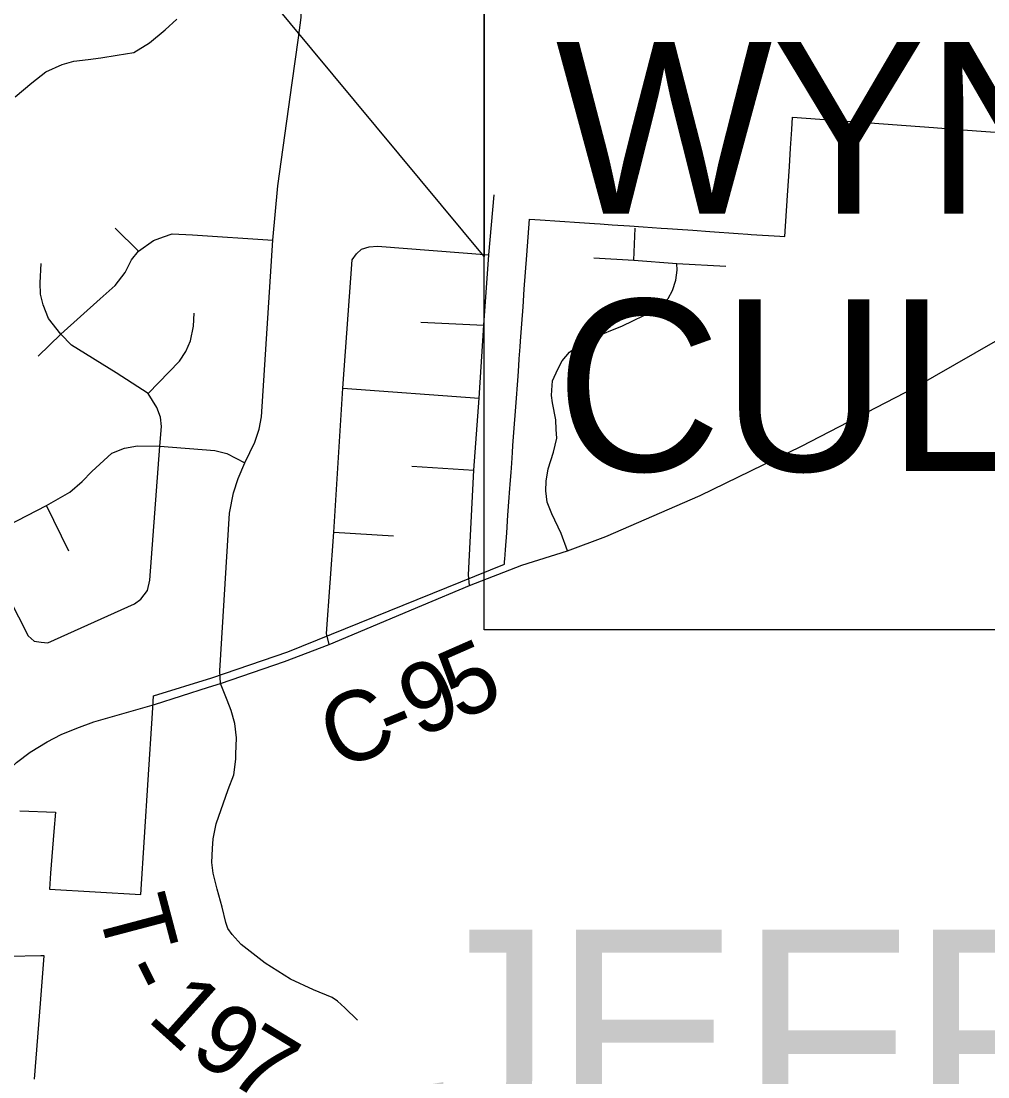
# Model space of a CAD drawing. Extents: x 208586767.6 to 208586821.4, y -134301046.9 to -134301022.9.
# Drawn here: x 208586780.726 to 208586781.515, y -134301029.317 to -134301028.455 of the extents above; entities that cross this region are included whole.
import ezdxf

# ---------------------------------------------------------------- set-up
doc = ezdxf.new("R2010")
doc.units = 0
for name, color, linetype in [('GM_X_City_Street', 7, 'Continuous'), ('GM_X_Corporation', 7, 'Continuous'), ('GM_X_County_Road', 7, 'Continuous'), ('GM_X_County_Road_Text', 7, 'Continuous'), ('GM_X_Minor_River', 7, 'Continuous'), ('GM_X_Township_Road', 7, 'Continuous'), ('GM_X_Township_Road_Text', 7, 'Continuous'), ('GM_X_Township_Text', 7, 'Continuous'), ('SH_Text', 7, 'Continuous')]:
    doc.layers.add(name, color=color, linetype=linetype)

msp = doc.modelspace()

# ---------------------------------------------------------------- linework, layer by layer
at = {"layer": 'GM_X_City_Street'}
for p, q in [((208586780.80313, -134301028.62414), (208586780.82208, -134301028.64308)), ((208586781.05241, -134301028.70091), (208586781.10392, -134301028.70348)), ((208586780.74037, -134301028.72874), (208586780.75892, -134301028.71058)), ((208586780.98885, -134301028.75479), (208586781.09997, -134301028.76289)), ((208586781.0451, -134301028.81854), (208586781.09563, -134301028.8217)), ((208586780.76524, -134301028.88782), (208586780.74702, -134301028.85063)), ((208586780.98155, -134301028.87222), (208586781.0301, -134301028.87538))]:
    msp.add_line(p, q, dxfattribs=at)
for points in [[(208586781.09227, -134301028.91585), (208586781.09122, -134301028.90716), (208586781.09563, -134301028.8217), (208586781.09997, -134301028.76289), (208586781.10392, -134301028.70348), (208586781.10806, -134301028.64605), (208586781.11221, -134301028.5971)], [(208586780.75892, -134301028.71058), (208586780.7909, -134301028.68177), (208586780.80313, -134301028.67111), (208586780.81142, -134301028.66046), (208586780.81655, -134301028.65019), (208586780.82208, -134301028.64308), (208586780.83432, -134301028.6344), (208586780.84261, -134301028.63125), (208586780.84971, -134301028.62888), (208586780.86629, -134301028.62967), (208586780.93182, -134301028.634)], [(208586780.97761, -134301028.9638), (208586780.97549, -134301028.95505), (208586780.98155, -134301028.87222), (208586780.98885, -134301028.75479), (208586780.99655, -134301028.64999), (208586780.99991, -134301028.64526), (208586781.00405, -134301028.64131), (208586781.01037, -134301028.63934), (208586781.01708, -134301028.63894), (208586781.10806, -134301028.64605)], [(208586780.6922, -134301028.87867), (208586780.73209, -134301028.95689), (208586780.73721, -134301028.96124), (208586780.74274, -134301028.96203), (208586780.74827, -134301028.96242), (208586780.81892, -134301028.93084), (208586780.82405, -134301028.92689), (208586780.82958, -134301028.91979), (208586780.83155, -134301028.9115), (208586780.83945, -134301028.80216), (208586780.84103, -134301028.78598), (208586780.84024, -134301028.77848), (208586780.83708, -134301028.77058), (208586780.82998, -134301028.75914), (208586780.80392, -134301028.74216), (208586780.76761, -134301028.71966), (208586780.75892, -134301028.71058), (208586780.74866, -134301028.69796), (208586780.74432, -134301028.6869), (208586780.74234, -134301028.67821), (208586780.74195, -134301028.66874), (208586780.74274, -134301028.65296)], [(208586780.82998, -134301028.75914), (208586780.85563, -134301028.73269), (208586780.86076, -134301028.72479), (208586780.86471, -134301028.71611), (208586780.86708, -134301028.70427), (208586780.86748, -134301028.69361)], [(208586780.57247, -134301028.91554), (208586780.59138, -134301028.9168), (208586780.60461, -134301028.91617), (208586780.62698, -134301028.91082), (208586780.6922, -134301028.87867), (208586780.74702, -134301028.85063), (208586780.76603, -134301028.83966), (208586780.77629, -134301028.83098), (208586780.78419, -134301028.82269), (208586780.80037, -134301028.80769), (208586780.81063, -134301028.80374), (208586780.82129, -134301028.80177), (208586780.83945, -134301028.80216), (208586780.88445, -134301028.80571), (208586780.89432, -134301028.80808), (208586780.90892, -134301028.81558)]]:
    msp.add_lwpolyline(points, dxfattribs=at)
at = {"layer": 'GM_X_Corporation'}
for points in [[(208586780.72535, -134301029.09969), (208586780.7544, -134301029.10066), (208586780.75316, -134301029.11655), (208586780.75051, -134301029.15048), (208586780.74948, -134301029.16362), (208586780.8242, -134301029.16794), (208586780.83018, -134301029.07445), (208586780.83366, -134301029.01994), (208586780.83454, -134301029.0057), (208586780.88194, -134301028.99115), (208586780.94385, -134301028.96983), (208586781.12063, -134301028.89836), (208586781.12078, -134301028.89625), (208586781.12092, -134301028.89424), (208586781.12146, -134301028.88677), (208586781.12248, -134301028.87271), (208586781.12353, -134301028.85832), (208586781.12456, -134301028.84397), (208586781.12483, -134301028.84027), (208586781.12558, -134301028.82991), (208586781.12604, -134301028.82346), (208586781.12658, -134301028.81603), (208586781.12722, -134301028.80719), (208586781.12763, -134301028.8015), (208586781.12814, -134301028.7945), (208586781.12865, -134301028.78738), (208586781.12966, -134301028.77351), (208586781.13068, -134301028.75936), (208586781.13095, -134301028.75565), (208586781.13173, -134301028.74487), (208586781.13232, -134301028.73662), (208586781.13275, -134301028.73076), (208586781.13345, -134301028.72106), (208586781.13378, -134301028.7165), (208586781.13481, -134301028.70231), (208586781.13581, -134301028.68839), (208586781.13685, -134301028.67409), (208586781.13785, -134301028.66026), (208586781.13886, -134301028.64624), (208586781.13992, -134301028.63165), (208586781.14099, -134301028.61682), (208586781.14984, -134301028.61742), (208586781.16594, -134301028.61853), (208586781.18189, -134301028.61962), (208586781.19423, -134301028.62047), (208586781.19861, -134301028.62077), (208586781.2084, -134301028.62144), (208586781.22257, -134301028.62241), (208586781.23391, -134301028.6232), (208586781.24852, -134301028.6242), (208586781.25378, -134301028.62456), (208586781.26175, -134301028.62511), (208586781.27435, -134301028.62598), (208586781.2883, -134301028.62694), (208586781.31135, -134301028.62853), (208586781.31919, -134301028.62907), (208586781.32202, -134301028.62926), (208586781.3454, -134301028.63087), (208586781.34942, -134301028.63115), (208586781.35156, -134301028.59762), (208586781.35308, -134301028.57398), (208586781.35404, -134301028.55888), (208586781.35501, -134301028.54382), (208586781.35566, -134301028.53359), (208586781.4706, -134301028.54212), (208586781.48741, -134301028.54337), (208586781.50558, -134301028.54472), (208586781.55151, -134301028.54813)], [(208586780.73736, -134301029.31845), (208586780.74218, -134301029.25686), (208586780.74522, -134301029.21801), (208586780.74239, -134301029.21806), (208586780.69045, -134301029.21895)]]:
    msp.add_lwpolyline(points, dxfattribs=at)
at = {"layer": 'GM_X_County_Road'}
msp.add_line((208586780.82195, -134301029.01662), (208586780.8315, -134301029.01393), dxfattribs=at)
for points in [[(208586780.87936, -134301028.99874), (208586780.88894, -134301028.99567), (208586780.94113, -134301028.9779), (208586780.97761, -134301028.9638), (208586781.0532, -134301028.93222), (208586781.09227, -134301028.91585), (208586781.13471, -134301028.89907), (208586781.17201, -134301028.88742), (208586781.20339, -134301028.87578), (208586781.28036, -134301028.84223), (208586781.36304, -134301028.8022), (208586781.45498, -134301028.7545), (208586781.5378, -134301028.70682)], [(208586780.8315, -134301029.01393), (208586780.83533, -134301029.01286), (208586780.87936, -134301028.99874)], [(208586780.69431, -134301029.08799), (208586780.69704, -134301029.08484), (208586780.70476, -134301029.0768), (208586780.72274, -134301029.06008), (208586780.73394, -134301029.05188), (208586780.74766, -134301029.04321), (208586780.75901, -134301029.03745), (208586780.77194, -134301029.03209), (208586780.78565, -134301029.02689), (208586780.80284, -134301029.022), (208586780.82195, -134301029.01662)]]:
    msp.add_lwpolyline(points, dxfattribs=at)
at = {"layer": 'GM_X_Minor_River'}
msp.add_lwpolyline([(208586780.7217, -134301028.51704), (208586780.73505, -134301028.50573), (208586780.74649, -134301028.49669), (208586780.75981, -134301028.4907), (208586780.76932, -134301028.4881), (208586780.78109, -134301028.48665), (208586780.79135, -134301028.48519), (208586780.80465, -134301028.483), (208586780.81832, -134301028.4808), (208586780.83128, -134301028.47291), (208586780.84387, -134301028.46236), (208586780.85341, -134301028.45368)], dxfattribs=at)
at = {"layer": 'GM_X_Township_Road'}
for p, q in [((208586781.22609, -134301028.65039), (208586781.22727, -134301028.62434)), ((208586781.26122, -134301028.65315), (208586781.30128, -134301028.65532))]:
    msp.add_line(p, q, dxfattribs=at)
for points in [[(208586780.88854, -134301028.98536), (208586780.89629, -134301028.85663), (208586780.89979, -134301028.84028), (208586780.90344, -134301028.82837), (208586780.90892, -134301028.81558), (208586780.91705, -134301028.79872), (208586780.9207, -134301028.78827), (208586780.9224, -134301028.77806), (208586780.93182, -134301028.634), (208586780.9359, -134301028.58979), (208586780.94741, -134301028.50557), (208586780.95257, -134301028.46896), (208586780.95481, -134301028.45229), (208586780.95532, -134301028.43304), (208586780.95515, -134301028.41723), (208586780.9537, -134301028.38523)], [(208586781.19352, -134301028.64841), (208586781.22609, -134301028.65039), (208586781.26122, -134301028.65315)], [(208586781.17201, -134301028.88742), (208586781.16688, -134301028.87341), (208586781.15938, -134301028.85723), (208586781.15563, -134301028.84776), (208586781.15444, -134301028.83867), (208586781.15464, -134301028.83078), (208586781.15642, -134301028.82071), (208586781.16056, -134301028.8069), (208586781.16332, -134301028.79545), (208586781.16293, -134301028.78855), (208586781.16253, -134301028.78065), (208586781.15977, -134301028.76664), (208586781.15898, -134301028.76071), (208586781.15938, -134301028.75637), (208586781.15997, -134301028.74887), (208586781.16431, -134301028.7392), (208586781.16786, -134301028.73249), (208586781.17379, -134301028.72539), (208586781.18089, -134301028.71986), (208586781.19273, -134301028.71374), (208586781.21701, -134301028.70387), (208586781.24286, -134301028.69144), (208586781.24859, -134301028.68729), (208586781.25411, -134301028.68157), (208586781.25786, -134301028.67506), (208586781.26043, -134301028.66657), (208586781.26141, -134301028.65848), (208586781.26122, -134301028.65315)], [(208586780.90161, -134301029.05334), (208586780.90211, -134301029.04003), (208586780.90081, -134301029.0285), (208586780.8978, -134301029.01781), (208586780.89461, -134301029.00937), (208586780.88894, -134301028.99567), (208586780.88854, -134301028.98536)], [(208586781.00068, -134301029.27047), (208586780.99046, -134301029.26025), (208586780.98458, -134301029.25502), (208586780.98001, -134301029.25198), (208586780.96499, -134301029.24567), (208586780.94607, -134301029.23696), (208586780.92561, -134301029.22391), (208586780.90603, -134301029.20867), (208586780.89862, -134301029.20063), (208586780.89493, -134301029.19562), (208586780.89341, -134301029.19083), (208586780.89036, -134301029.17821), (208586780.88644, -134301029.16363), (208586780.88296, -134301029.15036), (208586780.88187, -134301029.14187), (208586780.88253, -134301029.13034), (208586780.88296, -134301029.1225), (208586780.88557, -134301029.1101), (208586780.89536, -134301029.08225), (208586780.89993, -134301029.07028), (208586780.90146, -134301029.05744), (208586780.90161, -134301029.05334)]]:
    msp.add_lwpolyline(points, dxfattribs=at)
at = {"layer": 'SH_Text'}
for points in [[(208586781.10405, -134301028.37904), (208586781.10405, -134301028.64742), (208586780.48945, -134301027.90753)], [(208586781.10405, -134301028.37904), (208586783.37296, -134301028.37904), (208586783.37296, -134301028.95195), (208586781.10405, -134301028.95195)]]:
    msp.add_lwpolyline(points, close=True, dxfattribs=at)

# ---------------------------------------------------------------- texts
at = {"layer": 'GM_X_County_Road_Text'}
for s, rotation, p in [('5', 23.72321, (208586781.08363, -134301029.02648)), ('9', 22.60525, (208586781.0502, -134301029.04041)), ('C', 22.2725, (208586780.9851, -134301029.06711)), ('-', 22.34645, (208586781.02836, -134301029.04939))]:
    msp.add_text(s, height=0.05682, rotation=rotation, dxfattribs=at).set_placement(p)
at = {"layer": 'GM_X_Township_Road_Text'}
for s, rotation, p in [('T', 284.79919, (208586780.78823, -134301029.1777)), ('-', 296.64539, (208586780.80361, -134301029.23075)), ('1', 318.03765, (208586780.82802, -134301029.26989)), ('9', 327.39751, (208586780.86209, -134301029.29941)), ('7', 328.63382, (208586780.89271, -134301029.31898))]:
    msp.add_text(s, height=0.05682, rotation=rotation, dxfattribs=at).set_placement(p)
at = {"layer": 'GM_X_Township_Text'}
msp.add_text('JEFFERSON', height=0.170455, rotation=0.00001, dxfattribs=at).set_placement((208586781.04631, -134301029.36698))
at = {"layer": 'SH_Text'}
for s, p in [('WYNNE RIDGE CT          ', (208586781.16243, -134301028.61242)), ('CULVERT REPLACEMENT', (208586781.16243, -134301028.82242))]:
    msp.add_text(s, height=0.1399997, dxfattribs=at).set_placement(p)

doc.saveas('drawing.dxf')
